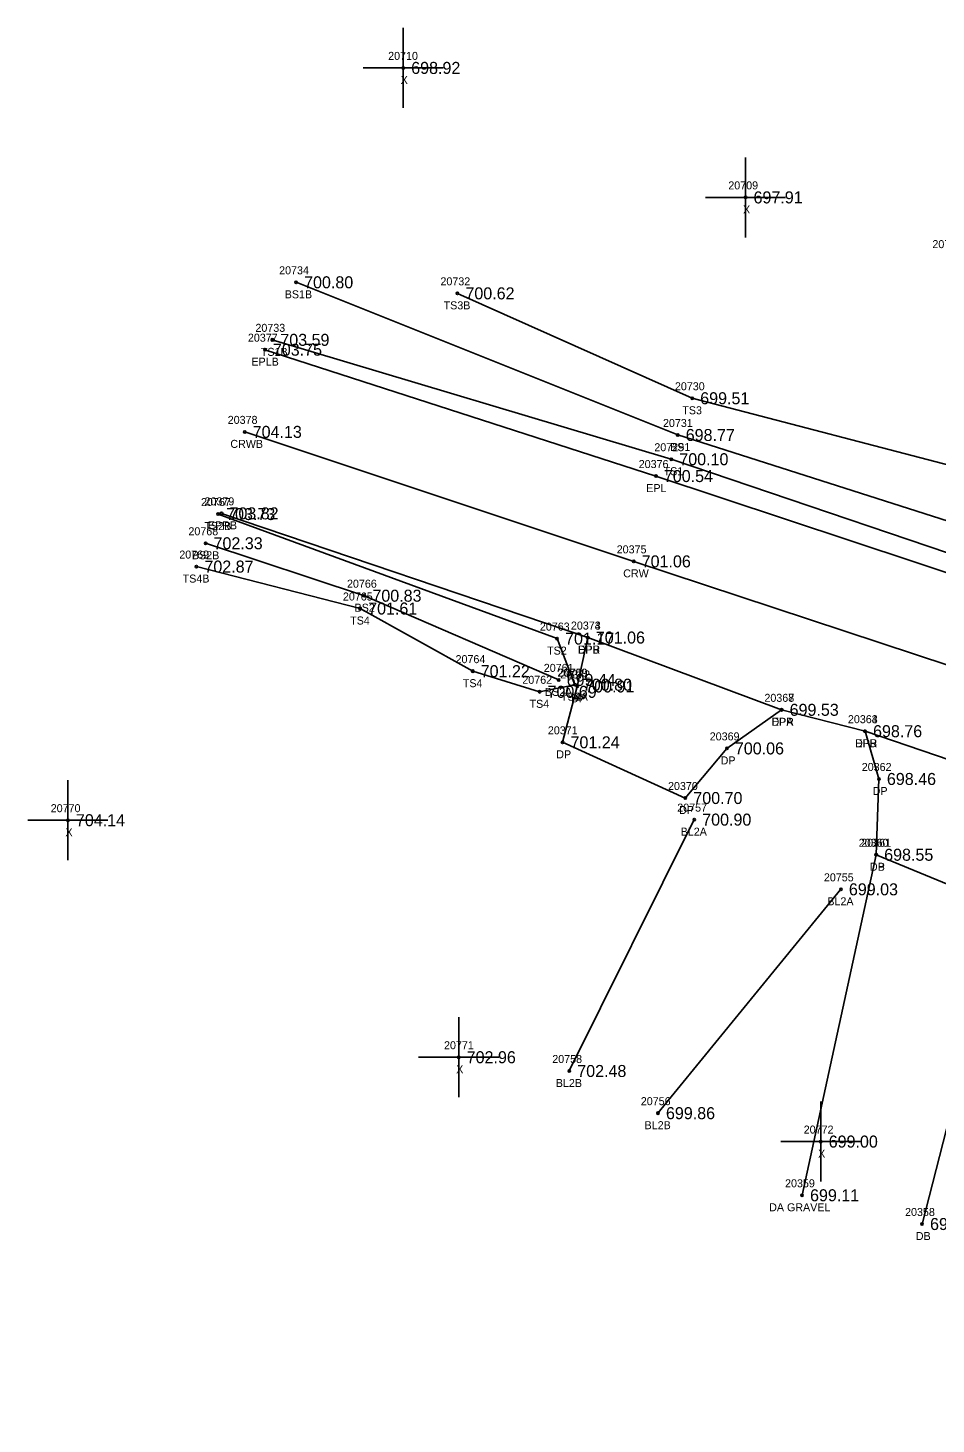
# Model space of a CAD drawing. Extents: x 1655675 to 1657082, y 1004080 to 1005193.
# Drawn here: x 1655674.7 to 1655788.1, y 1004723.9 to 1004898.3 of the extents above; entities that cross this region are included whole.
import ezdxf

# ---------------------------------------------------------------- set-up
doc = ezdxf.new("R2010")
doc.units = 0
for name, color, linetype in [('RD_DTM_BkLn1', 7, 'Continuous'), ('RD_DTM_BkLn2', 7, 'Continuous'), ('RD_DTM_BkLn_txCode', 7, 'Continuous'), ('RD_EX_Driveway', 7, 'Continuous'), ('RD_EX_Driveway_txCode', 7, 'Continuous'), ('RD_EX_Misc', 7, 'Continuous'), ('RD_EX_Misc_txCode', 7, 'Continuous'), ('RD_EX_Road', 7, 'Continuous'), ('RD_EX_Road_txCode', 7, 'Continuous'), ('RD_EX_TX_Driveway_ELEV', 7, 'Continuous'), ('RD_EX_TX_Misc_ELEV', 7, 'Continuous'), ('RD_EX_TX_Road_ELEV', 7, 'Continuous'), ('RD_HC_Survey_ELEV', 7, 'Continuous'), ('RD_HC_Survey_txCode', 7, 'Continuous'), ('RD_SMD_Locator', 7, 'Continuous')]:
    doc.layers.add(name, color=color, linetype=linetype)

msp = doc.modelspace()

# ---------------------------------------------------------------- linework, layer by layer
at = {"layer": 'RD_DTM_BkLn1'}
for p, q in [((1655757.88, 1004799.38), (1655742.27, 1004767.97)), ((1655776.2, 1004790.67), (1655753.35, 1004762.7))]:
    msp.add_line(p, q, dxfattribs=at)
msp.add_lwpolyline([(1656361.94, 1004629.69), (1656332.67, 1004639.45), (1656283.94, 1004655.24), (1656235.41, 1004671.18), (1656186.64, 1004687.32), (1656138.18, 1004703.47), (1656089.58, 1004719.78), (1656041.19, 1004735.88), (1655992.79, 1004752.04), (1655944.27, 1004768.13), (1655895.76, 1004783.85), (1655847.16, 1004799.72), (1655798.63, 1004815.7), (1655750.32, 1004831.65), (1655701.73, 1004847.83)], dxfattribs=at)
at = {"layer": 'RD_DTM_BkLn2'}
for points in [[(1656169.82, 1004711.08), (1656140.99, 1004718.68), (1656095.33, 1004733.78), (1656045.66, 1004750.66), (1655997.73, 1004765.48), (1655948.28, 1004782.13), (1655899.82, 1004798.93), (1655851.52, 1004814.56), (1655803.57, 1004832.22), (1655755.82, 1004847.44), (1655708.15, 1004866.52)], [(1656170.81, 1004710.38), (1656169.05, 1004714.04), (1656155.08, 1004721.39), (1656138.53, 1004726.1), (1656123.28, 1004729.96), (1656095.95, 1004735.19), (1656083.94, 1004739.91), (1656074.75, 1004751.62), (1656052.43, 1004759.33), (1656035.39, 1004767.92), (1656020.14, 1004775.42), (1656002.81, 1004778.08), (1655951.09, 1004790.04), (1655900.95, 1004804.56), (1655853.02, 1004819.57), (1655824.47, 1004830.21), (1655817.95, 1004830.44), (1655804.69, 1004834.86), (1655792.72, 1004842.88), (1655757.63, 1004852.03), (1655728.3, 1004865.14)], [(1656170.81, 1004710.38), (1656167.78, 1004708.02), (1656140.38, 1004715.48), (1656094.47, 1004730.71), (1656044.88, 1004747.29), (1655996.79, 1004763.35), (1655947.9, 1004779.96), (1655899.03, 1004795.71), (1655850.53, 1004811.22), (1655801.91, 1004828.51), (1655755.02, 1004844.41), (1655705.18, 1004859.33)], [(1655742.97, 1004816.24), (1655740.75, 1004822), (1655698.41, 1004837.56)], [(1655740.95, 1004816.84), (1655716.68, 1004827.36), (1655696.84, 1004833.91)], [(1655742.97, 1004816.24), (1655738.56, 1004815.35), (1655730.21, 1004817.93), (1655716.15, 1004825.76), (1655695.7, 1004831)]]:
    msp.add_lwpolyline(points, dxfattribs=at)
at = {"layer": 'RD_EX_Driveway'}
for p, q in [((1655771.35, 1004752.44), (1655780.61, 1004794.99)), ((1655796.48, 1004788.45), (1655786.34, 1004748.85))]:
    msp.add_line(p, q, dxfattribs=at)
for points in [[(1655768.8, 1004813.1), (1655761.96, 1004808.28), (1655756.77, 1004802.08), (1655741.43, 1004809.04), (1655743.27, 1004816.02), (1655744.59, 1004822.13)], [(1655805.73, 1004801.4), (1655800.2, 1004796.04), (1655796.48, 1004788.45), (1655780.61, 1004794.99), (1655780.95, 1004804.46), (1655779.22, 1004810.43)]]:
    msp.add_lwpolyline(points, dxfattribs=at)
at = {"layer": 'RD_EX_Misc'}
for p, q in [((1655721.53, 1004888.31), (1655721.53, 1004898.31)), ((1655716.53, 1004893.31), (1655726.53, 1004893.31)), ((1655764.29, 1004872.13), (1655764.29, 1004882.13)), ((1655759.29, 1004877.13), (1655769.29, 1004877.13)), ((1655679.65, 1004794.31), (1655679.65, 1004804.31)), ((1655674.65, 1004799.31), (1655684.65, 1004799.31)), ((1655728.46, 1004764.69), (1655728.46, 1004774.69)), ((1655723.46, 1004769.69), (1655733.46, 1004769.69)), ((1655773.68, 1004754.15), (1655773.68, 1004764.15)), ((1655768.68, 1004759.15), (1655778.68, 1004759.15))]:
    msp.add_line(p, q, dxfattribs=at)
at = {"layer": 'RD_EX_Road'}
for points in [[(1656365.12, 1004639.99), (1656336.04, 1004649.34), (1656302.55, 1004660.37), (1656279.15, 1004668.23), (1656240.07, 1004681.05), (1656188.23, 1004698.03), (1656166.72, 1004705.51), (1656141.16, 1004714.06), (1656093.11, 1004730.11), (1656044.16, 1004746.75), (1655996.36, 1004762.45), (1655947.2, 1004778.68), (1655899.09, 1004794.03), (1655850.62, 1004809.99), (1655801.91, 1004826.1), (1655753.09, 1004842.31), (1655704.25, 1004858.1)], [(1656358.5, 1004619.83), (1656328.78, 1004629.48), (1656280.77, 1004645.39), (1656247.66, 1004656.11), (1656244.5, 1004656.52), (1656222.03, 1004663.57), (1656217.65, 1004665.96), (1656183.42, 1004677.32), (1656134.59, 1004693.72), (1656086.19, 1004709.75), (1656037.58, 1004726.13), (1655989.57, 1004741.99), (1655940.62, 1004757.88), (1655892.37, 1004773.61), (1655843.48, 1004789.36), (1655805.73, 1004801.4), (1655779.22, 1004810.43), (1655768.8, 1004813.1), (1655744.59, 1004822.13), (1655698.83, 1004837.65)]]:
    msp.add_lwpolyline(points, dxfattribs=at)
at = {"layer": 'RD_SMD_Locator'}
for centre in [(1655721.53, 1004893.31), (1655764.29, 1004877.13), (1655708.15, 1004866.52), (1655728.3, 1004865.14), (1655704.25, 1004858.1), (1655705.18, 1004859.33), (1655757.63, 1004852.03), (1655701.73, 1004847.83), (1655755.82, 1004847.44), (1655755.02, 1004844.41), (1655753.09, 1004842.31), (1655698.41, 1004837.56), (1655698.83, 1004837.65), (1655696.84, 1004833.91), (1655750.32, 1004831.65), (1655695.7, 1004831), (1655716.68, 1004827.36), (1655716.15, 1004825.76), (1655740.75, 1004822), (1655744.59, 1004822.13), (1655744.59, 1004822.13), (1655730.21, 1004817.93), (1655740.95, 1004816.84), (1655742.97, 1004816.24), (1655742.97, 1004816.24), (1655743.27, 1004816.02), (1655738.56, 1004815.35), (1655768.8, 1004813.1), (1655768.8, 1004813.1), (1655741.43, 1004809.04), (1655779.22, 1004810.43), (1655779.22, 1004810.43), (1655761.96, 1004808.28), (1655780.95, 1004804.46), (1655756.77, 1004802.08), (1655679.65, 1004799.31), (1655757.88, 1004799.38), (1655780.61, 1004794.99), (1655780.61, 1004794.99), (1655776.2, 1004790.67), (1655728.46, 1004769.69), (1655742.27, 1004767.97), (1655753.35, 1004762.7), (1655773.68, 1004759.15), (1655771.35, 1004752.44), (1655786.34, 1004748.85)]:
    msp.add_circle(centre, 0.15, dxfattribs=at)

# ---------------------------------------------------------------- texts
at = {"layer": 'RD_DTM_BkLn_txCode'}
for s, p in [('20724', (1655787.63, 1004870.79)), ('20734', (1655706.03, 1004867.52)), ('20732', (1655726.18, 1004866.14)), ('BS1B', (1655706.73, 1004864.52)), ('TS3B', (1655726.58, 1004863.14)), ('20733', (1655703.07, 1004860.33)), ('TS1B', (1655703.75, 1004857.33)), ('20730', (1655755.47, 1004853.03)), ('TS3', (1655756.39, 1004850.03)), ('20731', (1655753.98, 1004848.44)), ('20729', (1655752.9, 1004845.41)), ('BS1', (1655754.87, 1004845.44)), ('TS1', (1655754.06, 1004842.41)), ('20767', (1655696.27, 1004838.56)), ('20768', (1655694.7, 1004834.91)), ('TS2B', (1655696.7, 1004835.56)), ('20769', (1655693.56, 1004832)), ('BS2B', (1655695.14, 1004831.91)), ('TS4B', (1655693.98, 1004829)), ('20766', (1655714.51, 1004828.36)), ('20765', (1655714, 1004826.76)), ('BS2', (1655715.45, 1004825.36)), ('TS4', (1655714.9, 1004823.76)), ('20763', (1655738.6, 1004823)), ('20764', (1655728.07, 1004818.93)), ('TS2', (1655739.5, 1004820)), ('20761', (1655739.09, 1004817.84)), ('20760', (1655740.79, 1004817.24)), ('20759', (1655740.85, 1004817.24)), ('TS4', (1655728.97, 1004815.93)), ('20762', (1655736.41, 1004816.35)), ('TS4', (1655737.31, 1004813.35)), ('BS2A', (1655739.23, 1004814.84)), ('TS2A', (1655741.24, 1004814.24)), ('TS4A', (1655741.24, 1004814.24)), ('20757', (1655755.76, 1004800.38)), ('BL2A', (1655756.19, 1004797.38)), ('20755', (1655774.08, 1004791.67)), ('BL2A', (1655774.51, 1004788.67)), ('20758', (1655740.15, 1004768.97)), ('BL2B', (1655740.59, 1004765.97)), ('20756', (1655751.21, 1004763.7)), ('BL2B', (1655751.68, 1004760.7))]:
    msp.add_text(s, height=1, dxfattribs=at).set_placement(p)
at = {"layer": 'RD_EX_Driveway_txCode'}
for s, p in [('20373', (1655742.48, 1004823.13)), ('DPB', (1655743.34, 1004820.13)), ('20372', (1655741.15, 1004817.02)), ('DP', (1655742.49, 1004814.02)), ('20368', (1655766.65, 1004814.1)), ('20371', (1655739.6, 1004810.04)), ('DPA', (1655767.53, 1004811.1)), ('20363', (1655777.08, 1004811.43)), ('20369', (1655759.82, 1004809.28)), ('DPB', (1655777.97, 1004808.43)), ('DP', (1655740.65, 1004807.04)), ('DP', (1655761.18, 1004806.28)), ('20362', (1655778.81, 1004805.46)), ('20370', (1655754.61, 1004803.08)), ('DP', (1655780.17, 1004802.46)), ('DP', (1655755.99, 1004800.08)), ('20360', (1655778.43, 1004795.99)), ('20361', (1655778.75, 1004795.99)), ('DB', (1655779.83, 1004792.99)), ('DP', (1655779.83, 1004792.99)), ('20359', (1655769.23, 1004753.44)), ('DA GRAVEL', (1655767.24, 1004750.44)), ('20358', (1655784.22, 1004749.85)), ('DB', (1655785.56, 1004746.85))]:
    msp.add_text(s, height=1, dxfattribs=at).set_placement(p)
at = {"layer": 'RD_EX_Misc_txCode'}
for s, p in [('20710', (1655719.65, 1004894.31)), ('X', (1655721.21, 1004891.31)), ('20709', (1655762.14, 1004878.13)), ('X', (1655763.98, 1004875.13)), ('20770', (1655677.5, 1004800.31)), ('X', (1655679.34, 1004797.31)), ('20771', (1655726.63, 1004770.69)), ('X', (1655728.15, 1004767.69)), ('20772', (1655771.56, 1004760.15)), ('X', (1655773.36, 1004757.15))]:
    msp.add_text(s, height=1, dxfattribs=at).set_placement(p)
at = {"layer": 'RD_EX_Road_txCode'}
for s, p in [('20377', (1655702.13, 1004859.1)), ('EPLB', (1655702.57, 1004856.1)), ('20376', (1655750.95, 1004843.31)), ('EPL', (1655751.89, 1004840.31)), ('20379', (1655696.71, 1004838.65)), ('EPRB', (1655697.13, 1004835.65)), ('20374', (1655742.48, 1004823.13)), ('EPR', (1655743.37, 1004820.13)), ('20367', (1655766.65, 1004814.1)), ('EPR', (1655767.57, 1004811.1)), ('20364', (1655777.08, 1004811.43)), ('EPR', (1655777.99, 1004808.43))]:
    msp.add_text(s, height=1, dxfattribs=at).set_placement(p)
at = {"layer": 'RD_EX_TX_Driveway_ELEV'}
for s, p in [('701.06', (1655745.59, 1004821.38)), ('700.91', (1655744.27, 1004815.27)), ('699.53', (1655769.8, 1004812.35)), ('698.76', (1655780.22, 1004809.68)), ('701.24', (1655742.43, 1004808.29)), ('700.06', (1655762.96, 1004807.53)), ('698.46', (1655781.95, 1004803.71)), ('700.70', (1655757.77, 1004801.33)), ('698.55', (1655781.61, 1004794.24)), ('698.55', (1655781.61, 1004794.24)), ('699.11', (1655772.35, 1004751.69)), ('699.19', (1655787.34, 1004748.1))]:
    msp.add_text(s, height=1.5, dxfattribs=at).set_placement(p)
at = {"layer": 'RD_EX_TX_Misc_ELEV'}
for s, p in [('698.92', (1655722.53, 1004892.56)), ('697.91', (1655765.29, 1004876.38)), ('700.80', (1655709.15, 1004865.77)), ('700.62', (1655729.3, 1004864.39)), ('703.59', (1655706.18, 1004858.58)), ('699.51', (1655758.63, 1004851.28)), ('698.77', (1655756.82, 1004846.69)), ('700.10', (1655756.02, 1004843.66)), ('703.73', (1655699.41, 1004836.81)), ('702.33', (1655697.84, 1004833.16)), ('702.87', (1655696.7, 1004830.25)), ('700.83', (1655717.68, 1004826.61)), ('701.61', (1655717.15, 1004825.01)), ('701.17', (1655741.75, 1004821.25)), ('701.22', (1655731.21, 1004817.18)), ('700.69', (1655739.56, 1004814.6)), ('699.44', (1655741.95, 1004816.09)), ('700.80', (1655743.97, 1004815.49)), ('700.80', (1655743.97, 1004815.49)), ('704.14', (1655680.65, 1004798.56)), ('700.90', (1655758.88, 1004798.63)), ('699.03', (1655777.2, 1004789.92)), ('702.96', (1655729.46, 1004768.94)), ('702.48', (1655743.27, 1004767.22)), ('699.86', (1655754.35, 1004761.95)), ('699.00', (1655774.68, 1004758.4))]:
    msp.add_text(s, height=1.5, dxfattribs=at).set_placement(p)
at = {"layer": 'RD_EX_TX_Road_ELEV'}
for s, p in [('703.75', (1655705.25, 1004857.35)), ('700.54', (1655754.09, 1004841.56)), ('703.82', (1655699.83, 1004836.9)), ('701.06', (1655745.59, 1004821.38)), ('699.53', (1655769.8, 1004812.35)), ('698.76', (1655780.22, 1004809.68))]:
    msp.add_text(s, height=1.5, dxfattribs=at).set_placement(p)
at = {"layer": 'RD_HC_Survey_ELEV'}
for s, p in [('704.13', (1655702.73, 1004847.08)), ('701.06', (1655751.32, 1004830.9))]:
    msp.add_text(s, height=1.5, dxfattribs=at).set_placement(p)
at = {"layer": 'RD_HC_Survey_txCode'}
for s, p in [('20378', (1655699.61, 1004848.83)), ('CRWB', (1655699.94, 1004845.83)), ('20375', (1655748.2, 1004832.65)), ('CRW', (1655749.01, 1004829.65))]:
    msp.add_text(s, height=1, dxfattribs=at).set_placement(p)

doc.saveas('drawing.dxf')
